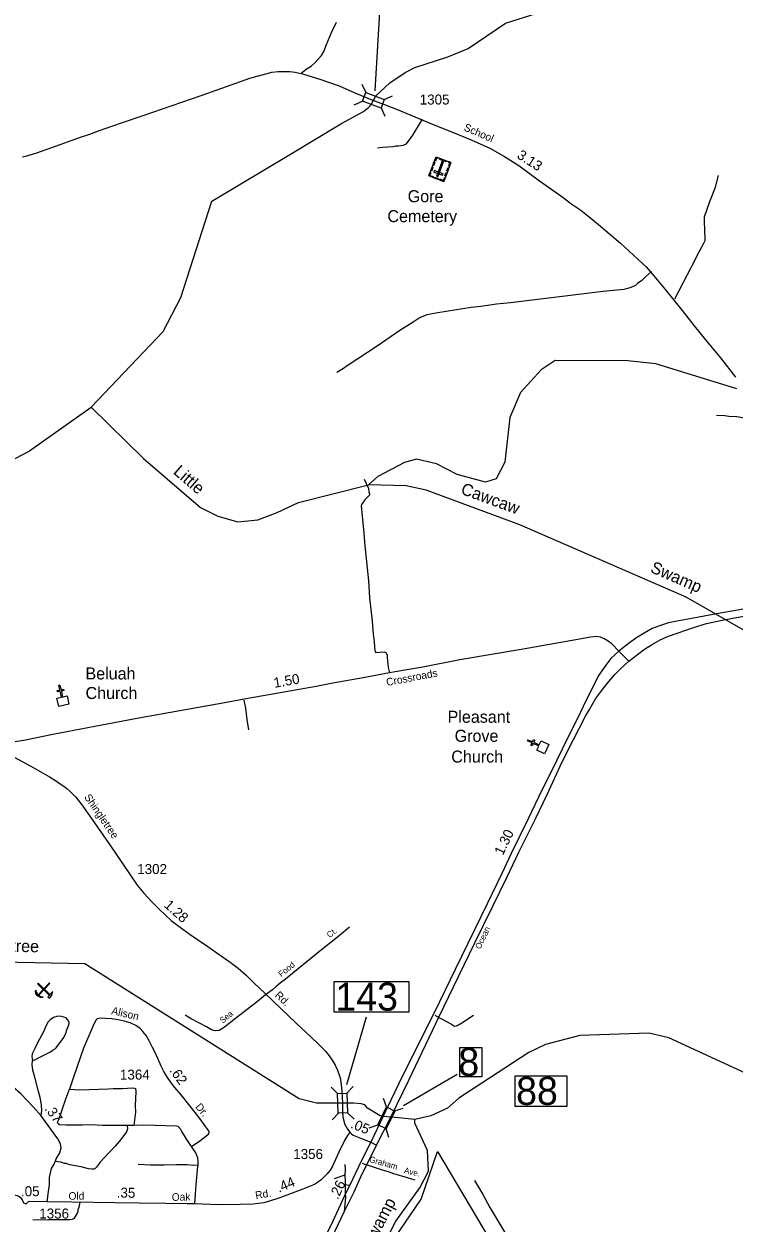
# Model space of a CAD drawing. Extents: x 2104537 to 2336408, y 34176 to 229611.
# Drawn here: x 2123652 to 2132514, y 60881 to 75855 of the extents above; entities that cross this region are included whole.
import ezdxf

# ---------------------------------------------------------------- set-up
doc = ezdxf.new("R2010")
doc.units = 0
for name, color, linetype in [('Exist Boundary Political City Limit New', 7, 'Continuous'), ('Exist Cultural Cemetery CELL', 7, 'Continuous'), ('Exist Cultural Cemetery Label', 7, 'Continuous'), ('Exist Cultural Church CELL', 7, 'Continuous'), ('Exist Cultural Church Label', 7, 'Continuous'), ('Exist Geographical Quarry CELL', 7, 'Continuous'), ('Exist Hydrographic Creek Single Shore', 7, 'Continuous'), ('Exist Hydrographic Misc Water Feature', 7, 'Continuous'), ('Exist Road Non-System Type 51', 7, 'Continuous'), ('Exist Road Non-System Type 51 Label', 7, 'Continuous'), ('Exist Road Primary US Divided Attributed', 7, 'Continuous'), ('Exist Road Primary US Label', 7, 'Continuous'), ('Exist Road Primary US Mileage Hundredths English Label', 7, 'Continuous'), ('Exist Road Primary US Structure Standard Bridge CELL', 7, 'Continuous'), ('Exist Road Primary US Structure Standard Bridge Number Label', 7, 'Continuous'), ('Exist Road Secondary Mileage Hundredths English Label', 7, 'Continuous'), ('Exist Road Secondary Structure Standard Bridge CELL', 7, 'Continuous'), ('Exist Road Secondary Structure Standard Bridge Number Label', 7, 'Continuous'), ('Exist Road Secondary Type 51 Attributed', 7, 'Continuous'), ('Exist Road Secondary Type 51 Label', 7, 'Continuous'), ('Exist Road Secondary Type 51 Number Label', 7, 'Continuous'), ('Map Preparation Boundary City Limit Buffer Line', 7, 'Continuous'), ('Old_Level_32', 7, 'Continuous')]:
    doc.layers.add(name, color=color, linetype=linetype)

msp = doc.modelspace()

# ---------------------------------------------------------------- linework, layer by layer
at = {"layer": 'Exist Boundary Political City Limit New'}
msp.add_lwpolyline([(2128280, 60697), (2128608, 61179), (2128812, 61776), (2129551, 60532)], dxfattribs=at)
at = {"layer": 'Exist Cultural Cemetery CELL'}
for points in [[(2128890, 73886), (2128704, 73957), (2128795, 74195), (2128981, 74124)], [(2128780, 74124), (2128764, 74083), (2128754, 74087), (2128769, 74128)], [(2128826, 74183), (2128822, 74173), (2128801, 74181), (2128787, 74143), (2128776, 74147), (2128795, 74195)], [(2128799, 73953), (2128816, 73946), (2128888, 74135), (2128871, 74142)], [(2128923, 74134), (2128844, 74164), (2128848, 74175), (2128927, 74145)], [(2128950, 74136), (2128946, 74125), (2128966, 74117), (2128952, 74080), (2128962, 74076), (2128981, 74124)], [(2128719, 73998), (2128730, 73994), (2128719, 73964), (2128757, 73949), (2128753, 73939), (2128704, 73957)], [(2128756, 74062), (2128741, 74022), (2128730, 74026), (2128746, 74066)], [(2128876, 73965), (2128883, 73982), (2128773, 74024), (2128766, 74006)], [(2128932, 73996), (2128917, 73956), (2128906, 73960), (2128921, 74000)], [(2128956, 74059), (2128941, 74018), (2128930, 74023), (2128945, 74063)], [(2128821, 73913), (2128772, 73931), (2128777, 73942), (2128825, 73923)], [(2128906, 73927), (2128895, 73931), (2128883, 73901), (2128846, 73915), (2128842, 73905), (2128890, 73886)]]:
    msp.add_lwpolyline(points, close=True, dxfattribs=at)
at = {"layer": 'Exist Cultural Church CELL'}
for points in [[(2124062, 67435), (2124118, 67447), (2124102, 67521), (2124071, 67515), (2124067, 67530), (2124098, 67537), (2124086, 67596), (2124101, 67599), (2124114, 67540), (2124145, 67547), (2124149, 67532), (2124118, 67525), (2124134, 67450), (2124190, 67463), (2124213, 67359), (2124085, 67331)], [(2130052, 66785), (2130076, 66837), (2130007, 66869), (2129993, 66840), (2129979, 66847), (2129993, 66876), (2129938, 66902), (2129945, 66917), (2130000, 66891), (2130013, 66920), (2130028, 66913), (2130014, 66884), (2130083, 66851), (2130108, 66903), (2130204, 66858), (2130148, 66740)]]:
    msp.add_lwpolyline(points, close=True, dxfattribs=at)
at = {"layer": 'Exist Geographical Quarry CELL'}
for points in [[(2123892, 63702), (2123885, 63700), (2123879, 63698), (2123869, 63697), (2123861, 63698), (2123849, 63702), (2123835, 63708), (2123823, 63716), (2123814, 63724), (2123807, 63734), (2123801, 63746), (2123798, 63756), (2123796, 63767), (2123797, 63779), (2123798, 63790), (2123801, 63775), (2123804, 63765), (2123807, 63758), (2123814, 63747), (2123821, 63737), (2123827, 63730), (2123839, 63721), (2123849, 63714), (2123861, 63708), (2123873, 63705), (2123885, 63703)], [(2123980, 63730), (2123972, 63722), (2123819, 63868), (2123827, 63876)], [(2123976, 63872), (2123969, 63879), (2123823, 63726), (2123830, 63719)], [(2123951, 63707), (2123970, 63688), (2123997, 63719), (2124011, 63772)]]:
    msp.add_lwpolyline(points, close=True, dxfattribs=at)
at = {"layer": 'Exist Hydrographic Creek Single Shore'}
for points in [[(2124491, 71070), (2125387, 72014), (2125609, 72439), (2125996, 73643), (2126977, 74231), (2127608, 74606), (2127889, 74760), (2127951, 74811), (2127986, 74850), (2128044, 74957), (2128217, 75118), (2128411, 75248), (2128532, 75312), (2128940, 75444), (2129196, 75550), (2129660, 75865), (2130651, 76181)], [(2119113, 69763), (2120355, 69568), (2120713, 69604), (2121603, 69908), (2122777, 70155), (2123410, 70356), (2123709, 70517), (2124491, 71070)], [(2124491, 71070), (2125144, 70430), (2125853, 69816), (2126071, 69710), (2126322, 69637), (2126572, 69661), (2126813, 69755), (2127078, 69881), (2127953, 70100)], [(2138306, 67331), (2136389, 67398), (2135512, 67825), (2134687, 67923), (2134071, 67921), (2133712, 67961), (2133262, 68059), (2132627, 68287), (2131917, 68695), (2129839, 69601), (2128670, 70031), (2128420, 70088), (2127953, 70100)], [(2128529, 62172), (2128487, 62177), (2128286, 62199), (2128182, 62209), (2128096, 62218), (2127941, 62316), (2127905, 62355), (2127860, 62370), (2127764, 62376), (2127655, 62376), (2127303, 62377), (2127087, 62433), (2124413, 64118), (2122937, 64147)], [(2136934, 60874), (2136884, 61049), (2136674, 61423), (2136599, 61464), (2135898, 61504), (2135732, 61553), (2135356, 61761), (2135114, 61759), (2134956, 61690), (2131700, 63193), (2131450, 63250), (2130591, 63221), (2130159, 63111), (2129951, 63010), (2129078, 62440), (2128937, 62315), (2128729, 62220), (2128529, 62172)], [(2128087, 60510), (2128293, 60903), (2128591, 61321), (2128699, 61529), (2128689, 61788), (2128530, 62129), (2128529, 62172)]]:
    msp.add_lwpolyline(points, dxfattribs=at)
at = {"layer": 'Exist Hydrographic Misc Water Feature'}
msp.add_lwpolyline([(2132548, 71298), (2131538, 71609), (2131188, 71649), (2130280, 71653), (2130105, 71535), (2129847, 71252), (2129716, 70942), (2129652, 70383), (2129544, 70175), (2129411, 70131), (2129060, 70230), (2128802, 70363), (2128552, 70420), (2128402, 70377), (2128069, 70203), (2127953, 70100)], dxfattribs=at)
at = {"layer": 'Exist Road Non-System Type 51'}
for p, q in [((2128781, 63477), (2128839, 63443)), ((2125024, 62100), (2124937, 62098)), ((2127873, 61628), (2127895, 61621)), ((2127895, 61621), (2127959, 61600)), ((2127656, 61477), (2127524, 61432)), ((2127656, 61477), (2127659, 61399)), ((2127659, 61399), (2127660, 61364)), ((2127660, 61364), (2127713, 61355)), ((2127660, 61364), (2127662, 61251)), ((2127662, 61251), (2127663, 61202)), ((2127663, 61202), (2127650, 61022))]:
    msp.add_line(p, q, dxfattribs=at)
for points in [[(2127116, 75243), (2127188, 75297), (2127235, 75327), (2127283, 75369), (2127363, 75460), (2127394, 75512), (2127426, 75600), (2127490, 75750), (2127551, 75876)], [(2128622, 74667), (2128501, 74465), (2128447, 74390), (2128417, 74354), (2128386, 74336), (2128326, 74328), (2128292, 74328), (2128260, 74319), (2128128, 74311), (2128066, 74303)], [(2131774, 72423), (2131988, 72830), (2132079, 73008), (2132143, 73125), (2132153, 73149), (2132154, 73171), (2132144, 73388), (2132145, 73445), (2132212, 73637), (2132284, 73819), (2132321, 73961)], [(2131486, 72762), (2131407, 72699), (2131363, 72651), (2131311, 72615), (2131283, 72591), (2131225, 72563), (2131201, 72555), (2131139, 72540), (2131099, 72534), (2130879, 72513), (2129726, 72372), (2129548, 72357), (2129354, 72328), (2129232, 72314), (2128817, 72248), (2128681, 72223), (2128607, 72195), (2128585, 72179), (2128509, 72133), (2128344, 72026), (2128060, 71831), (2127686, 71585), (2127640, 71551), (2127558, 71501)], [(2132956, 70924), (2132911, 70902), (2132874, 70896), (2132668, 70933), (2132620, 70937), (2132548, 70947), (2132448, 70952), (2132398, 70962), (2132296, 70967)], [(2127896, 70172), (2127950, 70053), (2127956, 70014), (2127965, 69989), (2127965, 69969), (2127907, 69912), (2127875, 69872), (2127865, 69856), (2127861, 69836), (2127895, 69498), (2127906, 69338), (2127952, 68900), (2127965, 68687), (2127996, 68399), (2128008, 68235), (2128023, 68135), (2128029, 68027), (2128037, 68017), (2128041, 68005), (2128149, 68013), (2128167, 68005), (2128175, 67988), (2128183, 67982), (2128183, 67945), (2128198, 67817), (2128213, 67752)], [(2126394, 67410), (2126416, 67312), (2126431, 67170), (2126454, 67040)], [(2127714, 64576), (2127587, 64469), (2127344, 64276), (2126917, 63928), (2126849, 63878), (2126794, 63832), (2126754, 63793), (2126668, 63729)], [(2126668, 63729), (2126567, 63647), (2126291, 63436), (2126156, 63325), (2126088, 63285), (2126038, 63280), (2125992, 63292), (2125930, 63332), (2125739, 63429), (2125665, 63477)], [(2124053, 63069), (2124150, 63196), (2124174, 63250), (2124188, 63294), (2124212, 63356), (2124214, 63386), (2124208, 63404), (2124176, 63444), (2124119, 63462), (2124073, 63464), (2124019, 63446), (2123980, 63419), (2123954, 63393), (2123922, 63333), (2123902, 63287), (2123847, 63175), (2123821, 63131), (2123791, 63069)], [(2128839, 63443), (2128853, 63435), (2128986, 63365), (2129024, 63339), (2129048, 63345), (2129076, 63358), (2129118, 63382), (2129261, 63477)], [(2124509, 63337), (2124394, 63064)], [(2123791, 63069), (2123752, 62993), (2123748, 62962), (2123752, 62936), (2123759, 62908)], [(2123759, 62908), (2123803, 62928), (2123840, 62948), (2123884, 62970), (2123939, 62997), (2123981, 63020), (2124017, 63043), (2124045, 63061), (2124053, 63069)], [(2124394, 63064), (2124265, 62688), (2124218, 62553)], [(2123864, 62218), (2123874, 62289), (2123872, 62352), (2123857, 62430), (2123833, 62523), (2123792, 62687), (2123762, 62791), (2123754, 62859), (2123759, 62908)], [(2124937, 62098), (2124871, 62100), (2124633, 62099), (2124487, 62106), (2124381, 62102), (2124176, 62101), (2124093, 62109), (2124077, 62119), (2124069, 62139), (2124085, 62175), (2124123, 62283), (2124172, 62433), (2124218, 62553)], [(2124218, 62553), (2124344, 62544), (2124708, 62555), (2124766, 62559), (2124880, 62560), (2125004, 62569), (2125030, 62567), (2125042, 62561), (2125046, 62523), (2125041, 62347), (2125043, 62265), (2125024, 62100)], [(2124940, 62098), (2124942, 62058), (2124930, 62020), (2124886, 61956), (2124838, 61899), (2124789, 61841), (2124714, 61760), (2124600, 61635), (2124570, 61595), (2124558, 61580), (2124534, 61558), (2124524, 61554), (2124500, 61552), (2124458, 61558), (2124364, 61582), (2124224, 61609), (2124180, 61623), (2124156, 61625), (2124112, 61639), (2124076, 61644), (2124040, 61653)], [(2125741, 61835), (2125676, 61937), (2125616, 62031), (2125608, 62049), (2125576, 62085), (2125554, 62091), (2125148, 62105), (2125024, 62100)], [(2125078, 61615), (2125230, 61608), (2125402, 61607), (2125556, 61611), (2125690, 61612), (2125766, 61604), (2125823, 61608)], [(2127658, 61611), (2127660, 61548), (2127656, 61477)], [(2127959, 61600), (2128124, 61546), (2128198, 61524), (2128262, 61498), (2128434, 61449), (2128474, 61435), (2128532, 61421)], [(2129274, 61413), (2129374, 61246), (2129467, 61073), (2129615, 60827), (2129766, 60574), (2129880, 60387)], [(2123316, 61385), (2123381, 61327), (2123407, 61281), (2123427, 61261), (2123449, 61251), (2123565, 61226), (2123585, 61218), (2123603, 61202), (2123619, 61182), (2123631, 61164), (2123646, 61132), (2123668, 61124), (2123688, 61124)], [(2123761, 60919), (2123955, 60924), (2124039, 60926), (2124106, 60924), (2124222, 60927), (2124257, 60931), (2124282, 60941), (2124318, 61003), (2124326, 61029), (2124328, 61049), (2124340, 61081), (2124353, 61140)]]:
    msp.add_lwpolyline(points, dxfattribs=at)
at = {"layer": 'Exist Road Primary US Divided Attributed'}
for points in [[(2134903, 68959), (2134576, 68898), (2134084, 68810), (2133498, 68706), (2132630, 68547), (2132249, 68479), (2132053, 68443), (2131779, 68394), (2131697, 68376), (2131582, 68340), (2131493, 68304), (2131391, 68249), (2131287, 68186), (2131192, 68116), (2131077, 68023)], [(2131201, 67896), (2131308, 67980), (2131398, 68048), (2131482, 68102), (2131593, 68165), (2131695, 68209), (2131804, 68247), (2131926, 68290), (2132062, 68334), (2132172, 68366), (2132367, 68409), (2132749, 68481), (2133224, 68565), (2133651, 68651), (2134241, 68755), (2134678, 68835), (2134855, 68867)], [(2131077, 68023), (2130977, 67930), (2130915, 67846), (2130871, 67788), (2130827, 67723), (2130759, 67593), (2130632, 67330), (2130563, 67188), (2130441, 66945), (2130302, 66662), (2130073, 66198), (2129944, 65928), (2129732, 65494), (2129614, 65246), (2129433, 64867), (2129034, 64046), (2128770, 63505), (2128376, 62719), (2128135, 62214)], [(2128230, 62204), (2128455, 62666), (2128834, 63462), (2129016, 63838), (2129276, 64370), (2129505, 64838), (2129679, 65196), (2129830, 65511), (2130034, 65928), (2130181, 66232), (2130370, 66640), (2130508, 66910), (2130660, 67210), (2130708, 67296), (2130786, 67426), (2130874, 67542), (2130950, 67642), (2131028, 67729), (2131095, 67803), (2131201, 67896)], [(2128135, 62214), (2127979, 61891)], [(2128052, 61853), (2128230, 62204)], [(2127979, 61891), (2127868, 61671), (2127750, 61424), (2127648, 61213), (2127480, 60849), (2127379, 60651)], [(2127452, 60616), (2127536, 60783), (2127650, 61022), (2127771, 61270), (2127850, 61451), (2128052, 61853)]]:
    msp.add_lwpolyline(points, dxfattribs=at)
at = {"layer": 'Exist Road Primary US Structure Standard Bridge CELL'}
for p, q in [((2128176, 62330), (2128140, 62437)), ((2128278, 62280), (2128385, 62317)), ((2127960, 62071), (2128067, 62108)), ((2128207, 61950), (2128171, 62057))]:
    msp.add_line(p, q, dxfattribs=at)
msp.add_lwpolyline([(2128067, 62108), (2128176, 62330), (2128280, 62279), (2128171, 62057)], close=True, dxfattribs=at)
at = {"layer": 'Exist Road Primary US Structure Standard Bridge Number Label'}
msp.add_line((2128387, 62349), (2129059, 62741), dxfattribs=at)
msp.add_lwpolyline([(2129090, 63075), (2129366, 63075), (2129366, 62706), (2129090, 62706)], close=True, dxfattribs=at)
at = {"layer": 'Exist Road Secondary Structure Standard Bridge CELL'}
for p, q in [((2127870, 75103), (2127917, 75000)), ((2127773, 74844), (2127876, 74891)), ((2128149, 74912), (2128252, 74958)), ((2128109, 74806), (2128156, 74703)), ((2127484, 62578), (2127566, 62500)), ((2127759, 62586), (2127682, 62503)), ((2127576, 62252), (2127498, 62170)), ((2127689, 62256), (2127771, 62178))]:
    msp.add_line(p, q, dxfattribs=at)
for points in [[(2127917, 75000), (2128149, 74912), (2128108, 74804), (2127876, 74891)], [(2127682, 62503), (2127689, 62256), (2127574, 62252), (2127566, 62500)]]:
    msp.add_lwpolyline(points, close=True, dxfattribs=at)
at = {"layer": 'Exist Road Secondary Structure Standard Bridge Number Label'}
for p, q in [((2128033, 75021), (2128097, 76075)), ((2127680, 62610), (2127928, 63457))]:
    msp.add_line(p, q, dxfattribs=at)
for points in [[(2127525, 63897), (2128454, 63897), (2128454, 63513), (2127525, 63513)], [(2129782, 62718), (2130426, 62718), (2130426, 62336), (2129782, 62336)]]:
    msp.add_lwpolyline(points, close=True, dxfattribs=at)
at = {"layer": 'Exist Road Secondary Type 51 Attributed'}
for points in [[(2123635, 74195), (2123688, 74207), (2123811, 74246), (2123998, 74313), (2124358, 74441), (2124463, 74475), (2124583, 74520), (2124867, 74619), (2125138, 74710), (2125863, 74961), (2126180, 75074), (2126472, 75178), (2126670, 75234), (2126746, 75252), (2126824, 75260), (2126887, 75262), (2126969, 75260), (2127037, 75252), (2127129, 75231), (2127355, 75160), (2127586, 75082), (2127783, 74994), (2128013, 74900)], [(2128013, 74900), (2128119, 74860), (2128300, 74793), (2128708, 74619), (2129070, 74474), (2129232, 74410), (2129466, 74303), (2129651, 74201), (2129827, 74088), (2130085, 73896), (2130364, 73701), (2130491, 73605), (2130600, 73531), (2130706, 73445), (2130821, 73351), (2131096, 73119), (2131315, 72917), (2131417, 72823), (2131493, 72734), (2131659, 72536), (2131866, 72278), (2132018, 72087), (2132159, 71911), (2132344, 71684), (2132534, 71446)], [(2131077, 68023), (2130989, 68115), (2130945, 68147), (2130894, 68176), (2130849, 68196), (2130803, 68204), (2130724, 68199), (2130610, 68177), (2129883, 68047), (2129090, 67913), (2128628, 67822), (2128406, 67787), (2128213, 67752), (2127887, 67688), (2127507, 67624), (2127297, 67582), (2126399, 67423), (2126179, 67381), (2125596, 67279), (2125083, 67186), (2124537, 67081), (2124011, 66981), (2123669, 66912), (2123334, 66858)], [(2131201, 67896), (2131077, 68023)], [(2123530, 66697), (2123736, 66586), (2123969, 66452), (2124043, 66406), (2124102, 66366), (2124147, 66335), (2124185, 66306), (2124228, 66268), (2124299, 66201), (2124375, 66104), (2124503, 65922), (2124703, 65634), (2124786, 65511), (2124888, 65359), (2125066, 65101), (2125147, 64999), (2125248, 64890), (2125338, 64801), (2125418, 64725), (2125490, 64660), (2125588, 64582), (2125727, 64486), (2125945, 64336), (2126100, 64227), (2126226, 64139), (2126324, 64064), (2126424, 63978), (2126526, 63876), (2126655, 63754), (2126858, 63559), (2127053, 63372), (2127236, 63201), (2127328, 63115), (2127414, 63029), (2127461, 62967), (2127497, 62916), (2127535, 62853), (2127565, 62791), (2127589, 62718), (2127601, 62679), (2127602, 62668), (2127611, 62605), (2127618, 62526), (2127626, 62376)], [(2125785, 61119), (2125791, 61242), (2125802, 61356), (2125817, 61544), (2125824, 61618), (2125825, 61650), (2125821, 61694), (2125815, 61717), (2125796, 61756), (2125741, 61835), (2125847, 61909), (2125960, 61996), (2125964, 62015), (2125954, 62038), (2125900, 62112), (2125845, 62186), (2125788, 62261), (2125727, 62342), (2125612, 62480), (2125533, 62573), (2125488, 62633), (2125441, 62698), (2125416, 62738), (2125397, 62775), (2125362, 62840), (2125291, 63002), (2125256, 63072), (2125214, 63157), (2125178, 63222), (2125137, 63274), (2125102, 63312), (2125049, 63348), (2124977, 63380), (2124930, 63393), (2124900, 63400), (2124827, 63417), (2124749, 63429), (2124671, 63437), (2124612, 63441), (2124584, 63436), (2124563, 63429), (2124548, 63415), (2124509, 63337)], [(2123941, 61145), (2123956, 61275), (2123968, 61361), (2123970, 61449), (2123997, 61561), (2124027, 61618), (2124052, 61684), (2124098, 61757), (2124115, 61821), (2124106, 61872), (2124073, 61934), (2123864, 62218), (2123770, 62327), (2123612, 62496), (2123510, 62587), (2123442, 62661), (2123390, 62702), (2123374, 62727), (2123382, 62779)], [(2127626, 62376), (2127627, 62269), (2127632, 62209), (2127642, 62154), (2127655, 62110), (2127688, 62053), (2127720, 62015)], [(2127720, 62015), (2127691, 61972), (2127654, 61911), (2127583, 61767), (2127502, 61591), (2127472, 61539), (2127437, 61496), (2127404, 61462), (2127362, 61419), (2127317, 61385), (2127279, 61364), (2127134, 61303), (2126831, 61192), (2126718, 61152), (2126646, 61134), (2126573, 61124), (2126511, 61118), (2126348, 61111), (2126074, 61109), (2125785, 61119)], [(2127720, 62015), (2127740, 61993), (2127759, 61979), (2127863, 61937), (2127979, 61891)], [(2127979, 61891), (2128052, 61853)], [(2123941, 61145), (2123720, 61148), (2123705, 61146), (2123695, 61139), (2123691, 61132), (2123688, 61124)], [(2125785, 61119), (2125689, 61120), (2125424, 61124), (2125088, 61128), (2124785, 61134), (2124249, 61141), (2123941, 61145)]]:
    msp.add_lwpolyline(points, dxfattribs=at)
at = {"layer": 'Map Preparation Boundary City Limit Buffer Line'}
msp.add_lwpolyline([(2128280, 60697), (2128608, 61179), (2128812, 61776), (2129551, 60532)], dxfattribs=at)

# ---------------------------------------------------------------- texts
at = {"layer": 'Exist Cultural Cemetery Label'}
for s, p in [('Gore', (2128441, 73629)), ('Cemetery', (2128188, 73380))]:
    msp.add_text(s, height=150, dxfattribs=at).set_placement(p)
at = {"layer": 'Exist Cultural Church Label'}
for s, p in [('Beluah', (2124419, 67669)), ('Church', (2124420, 67425)), ('Pleasant', (2128939, 67128)), ('Grove', (2129027, 66890)), ('Church', (2128985, 66631))]:
    msp.add_text(s, height=150, dxfattribs=at).set_placement(p)
at = {"layer": 'Exist Road Non-System Type 51 Label'}
for s, rotation, p in [('Ct.', 38.4023, (2127467, 64437)), ('Food', 39.2262, (2126864, 63948)), ('Sea', 39.1784, (2126131, 63369)), ('Graham', 343.849, (2127955, 61646)), ('Ave.', 346.7729, (2128390, 61505))]:
    msp.add_text(s, height=75, rotation=rotation, dxfattribs=at).set_placement(p)
at = {"layer": 'Exist Road Primary US Label'}
msp.add_text('Ocean', height=75, rotation=64.0172, dxfattribs=at).set_placement((2129346, 64294))
at = {"layer": 'Exist Road Primary US Mileage Hundredths English Label'}
for s, rotation, p in [('1.30', 64.1257, (2129628, 65464)), ('.26', 64.0265, (2127568, 61167))]:
    msp.add_text(s, height=125, rotation=rotation, dxfattribs=at).set_placement(p)
at = {"layer": 'Exist Road Primary US Structure Standard Bridge Number Label'}
msp.add_text('8', height=350, dxfattribs=at).set_placement((2129073, 62718))
at = {"layer": 'Exist Road Secondary Mileage Hundredths English Label'}
for s, rotation, p in [('3.13', 327.1888, (2129795, 74188)), ('1.50', 10.0014, (2126779, 67564)), ('1.28', 318.0655, (2125391, 64838)), ('.62', 305.1609, (2125463, 62784)), ('.37', 306.3142, (2123904, 62305)), ('.05', 337.9987, (2127719, 62073)), ('.44', 22.7664, (2126833, 61258)), ('.05', 0.3416, (2123614, 61215)), ('.35', 358.7404, (2124808, 61200))]:
    msp.add_text(s, height=125, rotation=rotation, dxfattribs=at).set_placement(p)
at = {"layer": 'Exist Road Secondary Structure Standard Bridge Number Label'}
for s, p in [('143', (2127538, 63533)), ('88', (2129794, 62356))]:
    msp.add_text(s, height=350, dxfattribs=at).set_placement(p)
at = {"layer": 'Exist Road Secondary Type 51 Label'}
for s, rotation, p in [('School', 336.724, (2129133, 74529)), ('Crossroads', 10.7704, (2128182, 67587)), ('Shingletree', 304.4929, (2124399, 66199)), ('Rd.', 316.8644, (2126775, 63716)), ('Alison', 347.0773, (2124737, 63490)), ('Dr.', 309.5372, (2125784, 62329)), ('Old', 0.6633, (2124208, 61171)), ('Oak', 1.4896, (2125497, 61157)), ('Rd.', 10.0394, (2126547, 61178))]:
    msp.add_text(s, height=95, rotation=rotation, dxfattribs=at).set_placement(p)
at = {"layer": 'Exist Road Secondary Type 51 Number Label'}
for s, p in [('1305', (2128591, 74849)), ('1302', (2125065, 65239)), ('1364', (2124849, 62672)), ('1356', (2127012, 61680)), ('1356', (2123842, 60937))]:
    msp.add_text(s, height=125, dxfattribs=at).set_placement(p)
at = {"layer": 'Old_Level_32'}
for s, rotation, p in [('Little', 319.1305, (2125505, 70248)), ('Cawcaw', 339.826, (2129093, 69990)), ('Swamp', 336.4325, (2131458, 69014)), ('Singletree', 358.8914, (2122935, 64279)), ('Swamp', 62.3309, (2127989, 60554))]:
    msp.add_text(s, height=150, rotation=rotation, dxfattribs=at).set_placement(p)

doc.saveas('drawing.dxf')
